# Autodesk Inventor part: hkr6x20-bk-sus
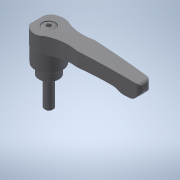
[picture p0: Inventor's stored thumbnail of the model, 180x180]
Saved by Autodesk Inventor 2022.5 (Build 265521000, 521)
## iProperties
Created: 2017-09
Part Number: hkr6x20-bk-sus
Material: 一般
Document SubType Name: Modeling
Designer: imaocorp
Density: 1 g/cm^3
Appearance: 既定
Author: imaocorp
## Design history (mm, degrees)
node "hkr6x20-bk-sus.x_t1"
node "hkr6x20-bk-sus"
node "Base1"
